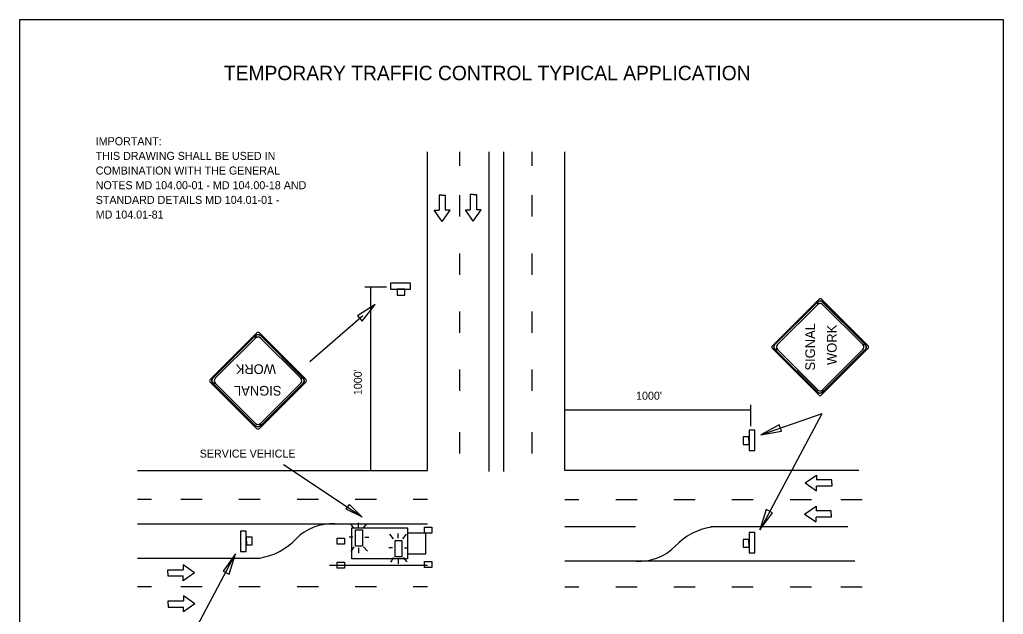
# Model space of a CAD drawing. Extents: x 1531.2 to 1538.6, y 1529.6 to 1539.9.
# Drawn here: x 1531.21 to 1538.58, y 1535.48 to 1539.94 of the extents above; entities that cross this region are included whole.
import ezdxf

# ---------------------------------------------------------------- set-up
doc = ezdxf.new("R2010")
doc.units = 0
for name, color, linetype in [('BORD-LINE', 7, 'Continuous'), ('DETL-DIMS', 7, 'Continuous'), ('DETL-LINE', 7, 'Continuous'), ('DETL-NOTE', 7, 'Continuous'), ('DETL-TITL', 7, 'Continuous'), ('USER-BORD', 7, 'Continuous')]:
    doc.layers.add(name, color=color, linetype=linetype)

# ---------------------------------------------------------------- blocks, each defined once
blk = doc.blocks.new('SIGN13')
at = {"layer": 'USER-BORD'}
for points in [[(-0.0134, 0.0182), (0.011, 0.0189), (0.011, 0.0371), (-0.0134, 0.0371)], [(-0.0314, 0.0182), (-0.0314, 0), (0.032, 0), (0.032, 0.0182)]]:
    blk.add_lwpolyline(points, close=True, dxfattribs=at)
blk = doc.blocks.new('DIR2')
at = {"layer": 'USER-BORD'}
for p, q in [((0, 0.0012), (-0.0342, -0.0477)), ((0, 0.0012), (0.0342, -0.0477)), ((-0.0342, -0.0477), (-0.0132, -0.0477)), ((-0.0132, -0.1133), (-0.0132, -0.0477)), ((0.0342, -0.0477), (0.0132, -0.0477)), ((0.0132, -0.1133), (0.0132, -0.0477)), ((-0.0011, -0.1133), (-0.0132, -0.1133)), ((-0.0011, -0.1133), (0.0011, -0.1133)), ((0.0011, -0.1133), (0.0132, -0.1133))]:
    blk.add_line(p, q, dxfattribs=at)
blk = doc.blocks.new('BAR')
at = {"layer": 'USER-BORD'}
for p, q in [((-0.011, 0.0696), (-0.0512, 0.1025)), ((0.0695, 0.1172), (0.0695, 0.0842)), ((0.15, 0.0732), (0.1866, 0.1062)), ((-0.0183, 0.0293), (-0.0585, 0.0293)), ((0.0037, 0.0037), (0.0037, 0.0622)), ((0.0037, 0.0622), (0.1427, 0.0622)), ((0.1427, 0.0037), (0.0037, 0.0037)), ((0.1427, 0.0622), (0.1427, 0.0037)), ((0.1573, 0.0293), (0.2049, 0.0293)), ((-0.011, -0.011), (-0.0512, -0.0403)), ((0.0658, -0.0183), (0.0658, -0.0513)), ((0.15, -0.011), (0.1902, -0.0366))]:
    blk.add_line(p, q, dxfattribs=at)

msp = doc.modelspace()

# ---------------------------------------------------------------- linework, layer by layer
at = {"layer": 'BORD-LINE'}
for p, q in [((1531.2124, 1531.0427), (1531.2124, 1539.9414)), ((1531.2124, 1539.9414), (1538.5844, 1539.9414)), ((1538.5844, 1539.9414), (1538.5844, 1531.0427))]:
    msp.add_line(p, q, dxfattribs=at)
at = {"layer": 'DETL-DIMS'}
for p, q in [((1533.9605, 1537.9355), (1533.8004, 1537.9355)), ((1533.8412, 1537.9355), (1533.8412, 1536.5602)), ((1533.7839, 1537.7207), (1533.3861, 1537.3741)), ((1536.6933, 1537.0127), (1535.2981, 1537.0127)), ((1536.6933, 1536.8932), (1536.6933, 1537.0532)), ((1537.2234, 1536.9859), (1536.7598, 1536.1123)), ((1537.2234, 1536.9859), (1536.7732, 1536.828)), ((1533.1907, 1536.6063), (1533.7791, 1536.214)), ((1532.3661, 1535.0612), (1532.8297, 1535.9347))]:
    msp.add_line(p, q, dxfattribs=at)
for points in [[(1533.7437, 1537.7195), (1533.779, 1537.681), (1533.877, 1537.8061)], [(1536.9225, 1536.8548), (1536.9049, 1536.904), (1536.766, 1536.8267)], [(1533.6585, 1536.2702), (1533.6835, 1536.3052), (1533.776, 1536.2129)], [(1536.8544, 1536.2436), (1536.8077, 1536.2673), (1536.76, 1536.1157)], [(1532.7365, 1535.806), (1532.7832, 1535.7827), (1532.8296, 1535.9347)]]:
    msp.add_lwpolyline(points, close=True, dxfattribs=at)
at = {"layer": 'DETL-LINE'}
for p, q in [((1534.2683, 1536.5602), (1534.2683, 1538.9501)), ((1534.5124, 1538.8456), (1534.5124, 1538.9501)), ((1534.7292, 1538.9501), (1534.7292, 1536.5518)), ((1534.8373, 1538.9501), (1534.8373, 1536.5518)), ((1535.054, 1538.8456), (1535.054, 1538.9501)), ((1535.2981, 1536.5602), (1535.2981, 1538.9501)), ((1534.5124, 1538.4645), (1534.5124, 1538.6246)), ((1535.054, 1538.4645), (1535.054, 1538.6246)), ((1534.5124, 1538.029), (1534.5124, 1538.189)), ((1535.054, 1538.029), (1535.054, 1538.189)), ((1537.2014, 1537.8439), (1536.8535, 1537.496)), ((1536.8731, 1537.5041), (1537.193, 1537.8241)), ((1537.193, 1537.8056), (1536.8915, 1537.5042)), ((1537.5701, 1537.4968), (1537.223, 1537.8439)), ((1537.5313, 1537.5041), (1537.2298, 1537.8056)), ((1537.2299, 1537.8241), (1537.5498, 1537.5041)), ((1534.5124, 1537.5934), (1534.5124, 1537.7535)), ((1535.054, 1537.5934), (1535.054, 1537.7535)), ((1532.9886, 1537.5917), (1532.6407, 1537.2437)), ((1533.3573, 1537.2445), (1533.0102, 1537.5917)), ((1532.6603, 1537.2519), (1532.9802, 1537.5718)), ((1532.9802, 1537.5534), (1532.6787, 1537.2519)), ((1533.3185, 1537.2519), (1533.017, 1537.5534)), ((1533.0171, 1537.5718), (1533.337, 1537.2519)), ((1536.8535, 1537.4745), (1537.2006, 1537.1273)), ((1537.193, 1537.1473), (1536.8731, 1537.4673)), ((1536.8915, 1537.4673), (1537.193, 1537.1658)), ((1537.2222, 1537.1273), (1537.5701, 1537.4753)), ((1537.5498, 1537.4673), (1537.2299, 1537.1473)), ((1537.2299, 1537.1658), (1537.5313, 1537.4673)), ((1534.5124, 1537.1579), (1534.5124, 1537.3179)), ((1535.054, 1537.1579), (1535.054, 1537.3179)), ((1532.6407, 1537.2223), (1532.9878, 1536.8751)), ((1532.9802, 1536.8951), (1532.6603, 1537.215)), ((1532.6787, 1537.215), (1532.9802, 1536.9135)), ((1533.0094, 1536.8751), (1533.3573, 1537.223)), ((1533.337, 1537.215), (1533.0171, 1536.8951)), ((1533.0171, 1536.9135), (1533.3185, 1537.215)), ((1534.5124, 1536.6889), (1534.5124, 1536.849)), ((1535.054, 1536.6889), (1535.054, 1536.849)), ((1532.0947, 1536.5602), (1534.2683, 1536.5602)), ((1537.5007, 1536.5602), (1535.2981, 1536.5602)), ((1532.1992, 1536.3441), (1532.0947, 1536.3441)), ((1532.5803, 1536.3441), (1532.4202, 1536.3441)), ((1533.0158, 1536.3441), (1532.8558, 1536.3441)), ((1533.4514, 1536.3441), (1533.2914, 1536.3441)), ((1533.887, 1536.3441), (1533.7269, 1536.3441)), ((1534.2683, 1536.3441), (1534.1625, 1536.3441)), ((1535.2981, 1536.3441), (1535.4039, 1536.3441)), ((1535.6795, 1536.3441), (1535.8395, 1536.3441)), ((1536.115, 1536.3441), (1536.275, 1536.3441)), ((1536.5506, 1536.3441), (1536.7106, 1536.3441)), ((1536.9862, 1536.3441), (1537.1462, 1536.3441)), ((1537.3672, 1536.3441), (1537.5272, 1536.3441)), ((1534.2683, 1536.1575), (1532.0947, 1536.1575)), ((1533.703, 1535.8985), (1533.703, 1536.1313)), ((1533.703, 1536.1313), (1534.1179, 1536.1313)), ((1534.1179, 1536.1313), (1534.1179, 1535.8985)), ((1535.8284, 1536.1373), (1535.2981, 1536.1373)), ((1537.4194, 1536.1373), (1536.3921, 1536.1373)), ((1534.2575, 1536.0899), (1534.1179, 1536.0899)), ((1534.1179, 1536.0899), (1534.1179, 1535.9364)), ((1534.2575, 1535.9364), (1534.2575, 1536.0899)), ((1532.0947, 1535.9027), (1533.009, 1535.9027)), ((1534.1179, 1535.8985), (1533.703, 1535.8985)), ((1534.1179, 1535.9364), (1534.2575, 1535.9364)), ((1535.2981, 1535.8825), (1537.4718, 1535.8825)), ((1533.5356, 1535.8508), (1534.2683, 1535.8508)), ((1532.1992, 1535.6876), (1532.0947, 1535.6876)), ((1532.5803, 1535.6876), (1532.4202, 1535.6876)), ((1533.0158, 1535.6876), (1532.8558, 1535.6876)), ((1533.4514, 1535.6876), (1533.2914, 1535.6876)), ((1533.887, 1535.6876), (1533.7269, 1535.6876)), ((1534.2683, 1535.6876), (1534.1625, 1535.6876)), ((1535.2981, 1535.6876), (1535.4039, 1535.6876)), ((1535.6795, 1535.6876), (1535.8395, 1535.6876)), ((1536.115, 1535.6876), (1536.275, 1535.6876)), ((1536.5506, 1535.6876), (1536.7106, 1535.6876)), ((1536.9862, 1535.6876), (1537.1462, 1535.6876)), ((1537.3672, 1535.6876), (1537.5272, 1535.6876))]:
    msp.add_line(p, q, dxfattribs=at)
for points in [[(1536.8731, 1537.5041), (1537.1838, 1537.8148), (1537.1941, 1537.8251), (1537.193, 1537.8056), (1536.8915, 1537.5042), (1536.8867, 1537.4977), (1536.884, 1537.488), (1536.8847, 1537.4792), (1536.8871, 1537.4731), (1536.8915, 1537.4673), (1536.8731, 1537.4673), (1536.8678, 1537.4747), (1536.8654, 1537.4847), (1536.8662, 1537.4921), (1536.8686, 1537.4981)], [(1537.2298, 1537.824), (1537.5405, 1537.5133), (1537.5508, 1537.503), (1537.5313, 1537.5041), (1537.2299, 1537.8056), (1537.2234, 1537.8104), (1537.2137, 1537.8131), (1537.2049, 1537.8124), (1537.1988, 1537.81), (1537.193, 1537.8056), (1537.193, 1537.824), (1537.2004, 1537.8293), (1537.2105, 1537.8317), (1537.2178, 1537.8309), (1537.2239, 1537.8285)], [(1533.017, 1537.5718), (1533.3277, 1537.2611), (1533.338, 1537.2507), (1533.3185, 1537.2519), (1533.0171, 1537.5534), (1533.0106, 1537.5581), (1533.0009, 1537.5609), (1532.9921, 1537.5602), (1532.986, 1537.5578), (1532.9802, 1537.5534), (1532.9802, 1537.5718), (1532.9876, 1537.577), (1532.9977, 1537.5794), (1533.005, 1537.5787), (1533.0111, 1537.5763)], [(1532.6603, 1537.2519), (1532.971, 1537.5625), (1532.9813, 1537.5729), (1532.9802, 1537.5534), (1532.6787, 1537.2519), (1532.6739, 1537.2454), (1532.6712, 1537.2358), (1532.6719, 1537.2269), (1532.6743, 1537.2209), (1532.6787, 1537.215), (1532.6603, 1537.215), (1532.655, 1537.2225), (1532.6526, 1537.2325), (1532.6534, 1537.2399), (1532.6558, 1537.2459)], [(1537.193, 1537.1474), (1536.8823, 1537.4581), (1536.872, 1537.4684), (1536.8915, 1537.4673), (1537.1929, 1537.1658), (1537.1994, 1537.161), (1537.2091, 1537.1583), (1537.218, 1537.159), (1537.224, 1537.1614), (1537.2298, 1537.1658), (1537.2298, 1537.1474), (1537.2224, 1537.1421), (1537.2124, 1537.1397), (1537.205, 1537.1405), (1537.199, 1537.1429)], [(1537.5497, 1537.4673), (1537.239, 1537.1566), (1537.2287, 1537.1463), (1537.2298, 1537.1658), (1537.5313, 1537.4672), (1537.5361, 1537.4737), (1537.5388, 1537.4834), (1537.5381, 1537.4922), (1537.5357, 1537.4983), (1537.5313, 1537.5041), (1537.5497, 1537.5041), (1537.555, 1537.4967), (1537.5574, 1537.4867), (1537.5566, 1537.4793), (1537.5542, 1537.4733)], [(1532.9802, 1536.8951), (1532.6695, 1537.2058), (1532.6592, 1537.2162), (1532.6787, 1537.215), (1532.9801, 1536.9135), (1532.9866, 1536.9088), (1532.9963, 1536.906), (1533.0052, 1536.9067), (1533.0112, 1536.9091), (1533.017, 1536.9135), (1533.017, 1536.8951), (1533.0096, 1536.8899), (1532.9996, 1536.8875), (1532.9922, 1536.8883), (1532.9862, 1536.8906)], [(1533.3369, 1537.215), (1533.0262, 1536.9043), (1533.0159, 1536.894), (1533.017, 1536.9135), (1533.3185, 1537.215), (1533.3233, 1537.2215), (1533.326, 1537.2311), (1533.3253, 1537.24), (1533.3229, 1537.2461), (1533.3185, 1537.2519), (1533.3369, 1537.2519), (1533.3422, 1537.2444), (1533.3446, 1537.2344), (1533.3438, 1537.2271), (1533.3414, 1537.221)], [(1534.2465, 1536.0893), (1534.2465, 1536.1345), (1534.3001, 1536.1345), (1534.3001, 1536.0893)], [(1533.5929, 1536.0078), (1533.5929, 1536.053), (1533.6465, 1536.053), (1533.6465, 1536.0078)], [(1533.5929, 1535.8291), (1533.5929, 1535.8742), (1533.6465, 1535.8742), (1533.6465, 1535.8291)], [(1534.2465, 1535.8325), (1534.2465, 1535.8777), (1534.3001, 1535.8777), (1534.3001, 1535.8325)]]:
    msp.add_lwpolyline(points, close=True, dxfattribs=at)
for centre, radius, start, end in [((1537.2115, 1537.8056), 0.0261, 45, 135), ((1537.2114, 1537.7872), 0.0261, 45, 135), ((1537.2122, 1537.8332), 0.0152, 45, 135), ((1532.9987, 1537.5534), 0.0261, 45, 135), ((1532.9994, 1537.5809), 0.0152, 45, 135), ((1532.9986, 1537.5349), 0.0261, 45, 135), ((1536.8643, 1537.4852), 0.0152, 135, 225), ((1536.8915, 1537.4857), 0.0261, 135, 225), ((1536.91, 1537.4857), 0.0261, 135, 225), ((1537.5129, 1537.4857), 0.0261, 315, 45), ((1537.5314, 1537.4857), 0.0261, 315, 45), ((1537.5593, 1537.486), 0.0152, 315, 45), ((1532.6515, 1537.233), 0.0152, 135, 225), ((1532.6787, 1537.2335), 0.0261, 135, 225), ((1532.6972, 1537.2335), 0.0261, 135, 225), ((1533.3001, 1537.2335), 0.0261, 315, 45), ((1533.3186, 1537.2335), 0.0261, 315, 45), ((1533.3465, 1537.2338), 0.0152, 315, 45), ((1537.2114, 1537.1842), 0.0261, 225, 315), ((1537.2115, 1537.1658), 0.0261, 225, 315), ((1537.2114, 1537.1381), 0.0152, 225, 315), ((1532.9986, 1536.932), 0.0261, 225, 315), ((1532.9987, 1536.9135), 0.0261, 225, 315), ((1532.9986, 1536.8859), 0.0152, 225, 315), ((1533.5487, 1535.7922), 0.368, 85.77982, 136.30608), ((1536.4729, 1535.6621), 0.4798, 99.15343, 136.30608), ((1532.9358, 1536.3778), 0.4798, 279.15343, 316.30608), ((1535.8599, 1536.2478), 0.368, 265.77982, 316.30608)]:
    msp.add_arc(centre, radius, start, end, dxfattribs=at)

# ---------------------------------------------------------------- block references
at = {"layer": 'DETL-LINE', "xscale": 1.7422373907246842, "yscale": -1.742237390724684}
for p in [(1534.3792, 1538.4287), (1534.6122, 1538.4322)]:
    msp.add_blockref('DIR2', p, dxfattribs=at)
at = {"layer": 'DETL-LINE'}
for name, p, xscale, yscale, rotation in [('SIGN13', (1534.0674, 1537.9647), 2.391312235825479, 2.391312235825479, 179.99999999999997), ('SIGN13', (1536.7224, 1536.7863), 2.391312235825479, 2.391312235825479, 89.99999999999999), ('DIR2', (1537.101, 1536.4668), 1.7422373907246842, 1.742237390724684, 90), ('DIR2', (1537.0975, 1536.2339), 1.7422373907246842, 1.742237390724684, 90), ('SIGN13', (1532.867, 1536.0295), 2.391312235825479, 2.391312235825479, -90.00000000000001), ('BAR', (1533.7263, 1536.1179), 0.8711186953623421, 0.871118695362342, -90.00000000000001), ('BAR', (1534.0226, 1536.0381), 0.8711186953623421, 0.871118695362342, -90.00000000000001), ('SIGN13', (1536.7224, 1536.0177), 2.391312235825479, 2.391312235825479, 89.99999999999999), ('DIR2', (1532.5199, 1535.7927), 1.7422373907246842, -1.742237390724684, 89.99999999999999), ('DIR2', (1532.5235, 1535.5597), 1.7422373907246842, -1.742237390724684, 89.99999999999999)]:
    msp.add_blockref(name, p, dxfattribs=dict(at, xscale=xscale, yscale=yscale, rotation=rotation))

# ---------------------------------------------------------------- texts
for s, rotation, p in [('SIGNAL', 90, (1537.1731, 1537.3098)), ('WORK', 90, (1537.3354, 1537.3515)), ('WORK', 180, (1533.1328, 1537.3571)), ('SIGNAL', 180, (1533.1746, 1537.1946))]:
    msp.add_text(s, height=0.07256, rotation=rotation, dxfattribs=at).set_placement(p)
at = {"layer": 'DETL-NOTE'}
for s, p in [('IMPORTANT:', (1531.7823, 1538.9999)), ('THIS DRAWING SHALL BE USED IN', (1531.7823, 1538.8899)), ('COMBINATION WITH THE GENERAL', (1531.7823, 1538.7799)), ('NOTES MD 104.00-01 - MD 104.00-18 AND', (1531.7823, 1538.6699)), ('STANDARD DETAILS MD 104.01-01 -', (1531.7823, 1538.5599)), ('MD 104.01-81', (1531.7823, 1538.4499)), ("1000'", (1535.8319, 1537.0912)), ('SERVICE VEHICLE', (1532.5616, 1536.6571))]:
    msp.add_text(s, height=0.06, dxfattribs=at).set_placement(p)
msp.add_text("1000'", height=0.06, rotation=90, dxfattribs=at).set_placement((1533.7765, 1537.1253))
at = {"layer": 'DETL-TITL'}
msp.add_text('TEMPORARY TRAFFIC CONTROL TYPICAL APPLICATION', height=0.108, dxfattribs=at).set_placement((1532.7424, 1539.4874))

doc.saveas('drawing.dxf')
